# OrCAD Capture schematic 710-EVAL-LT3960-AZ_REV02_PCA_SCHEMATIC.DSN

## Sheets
1 PAGE1: size Custom; title: 2; company: ANALOG DEVICES; note: DEMO BOARD BILL OF MATERIALS; note: I  C TO CAN-PHYSICAL TRANSCEIVER
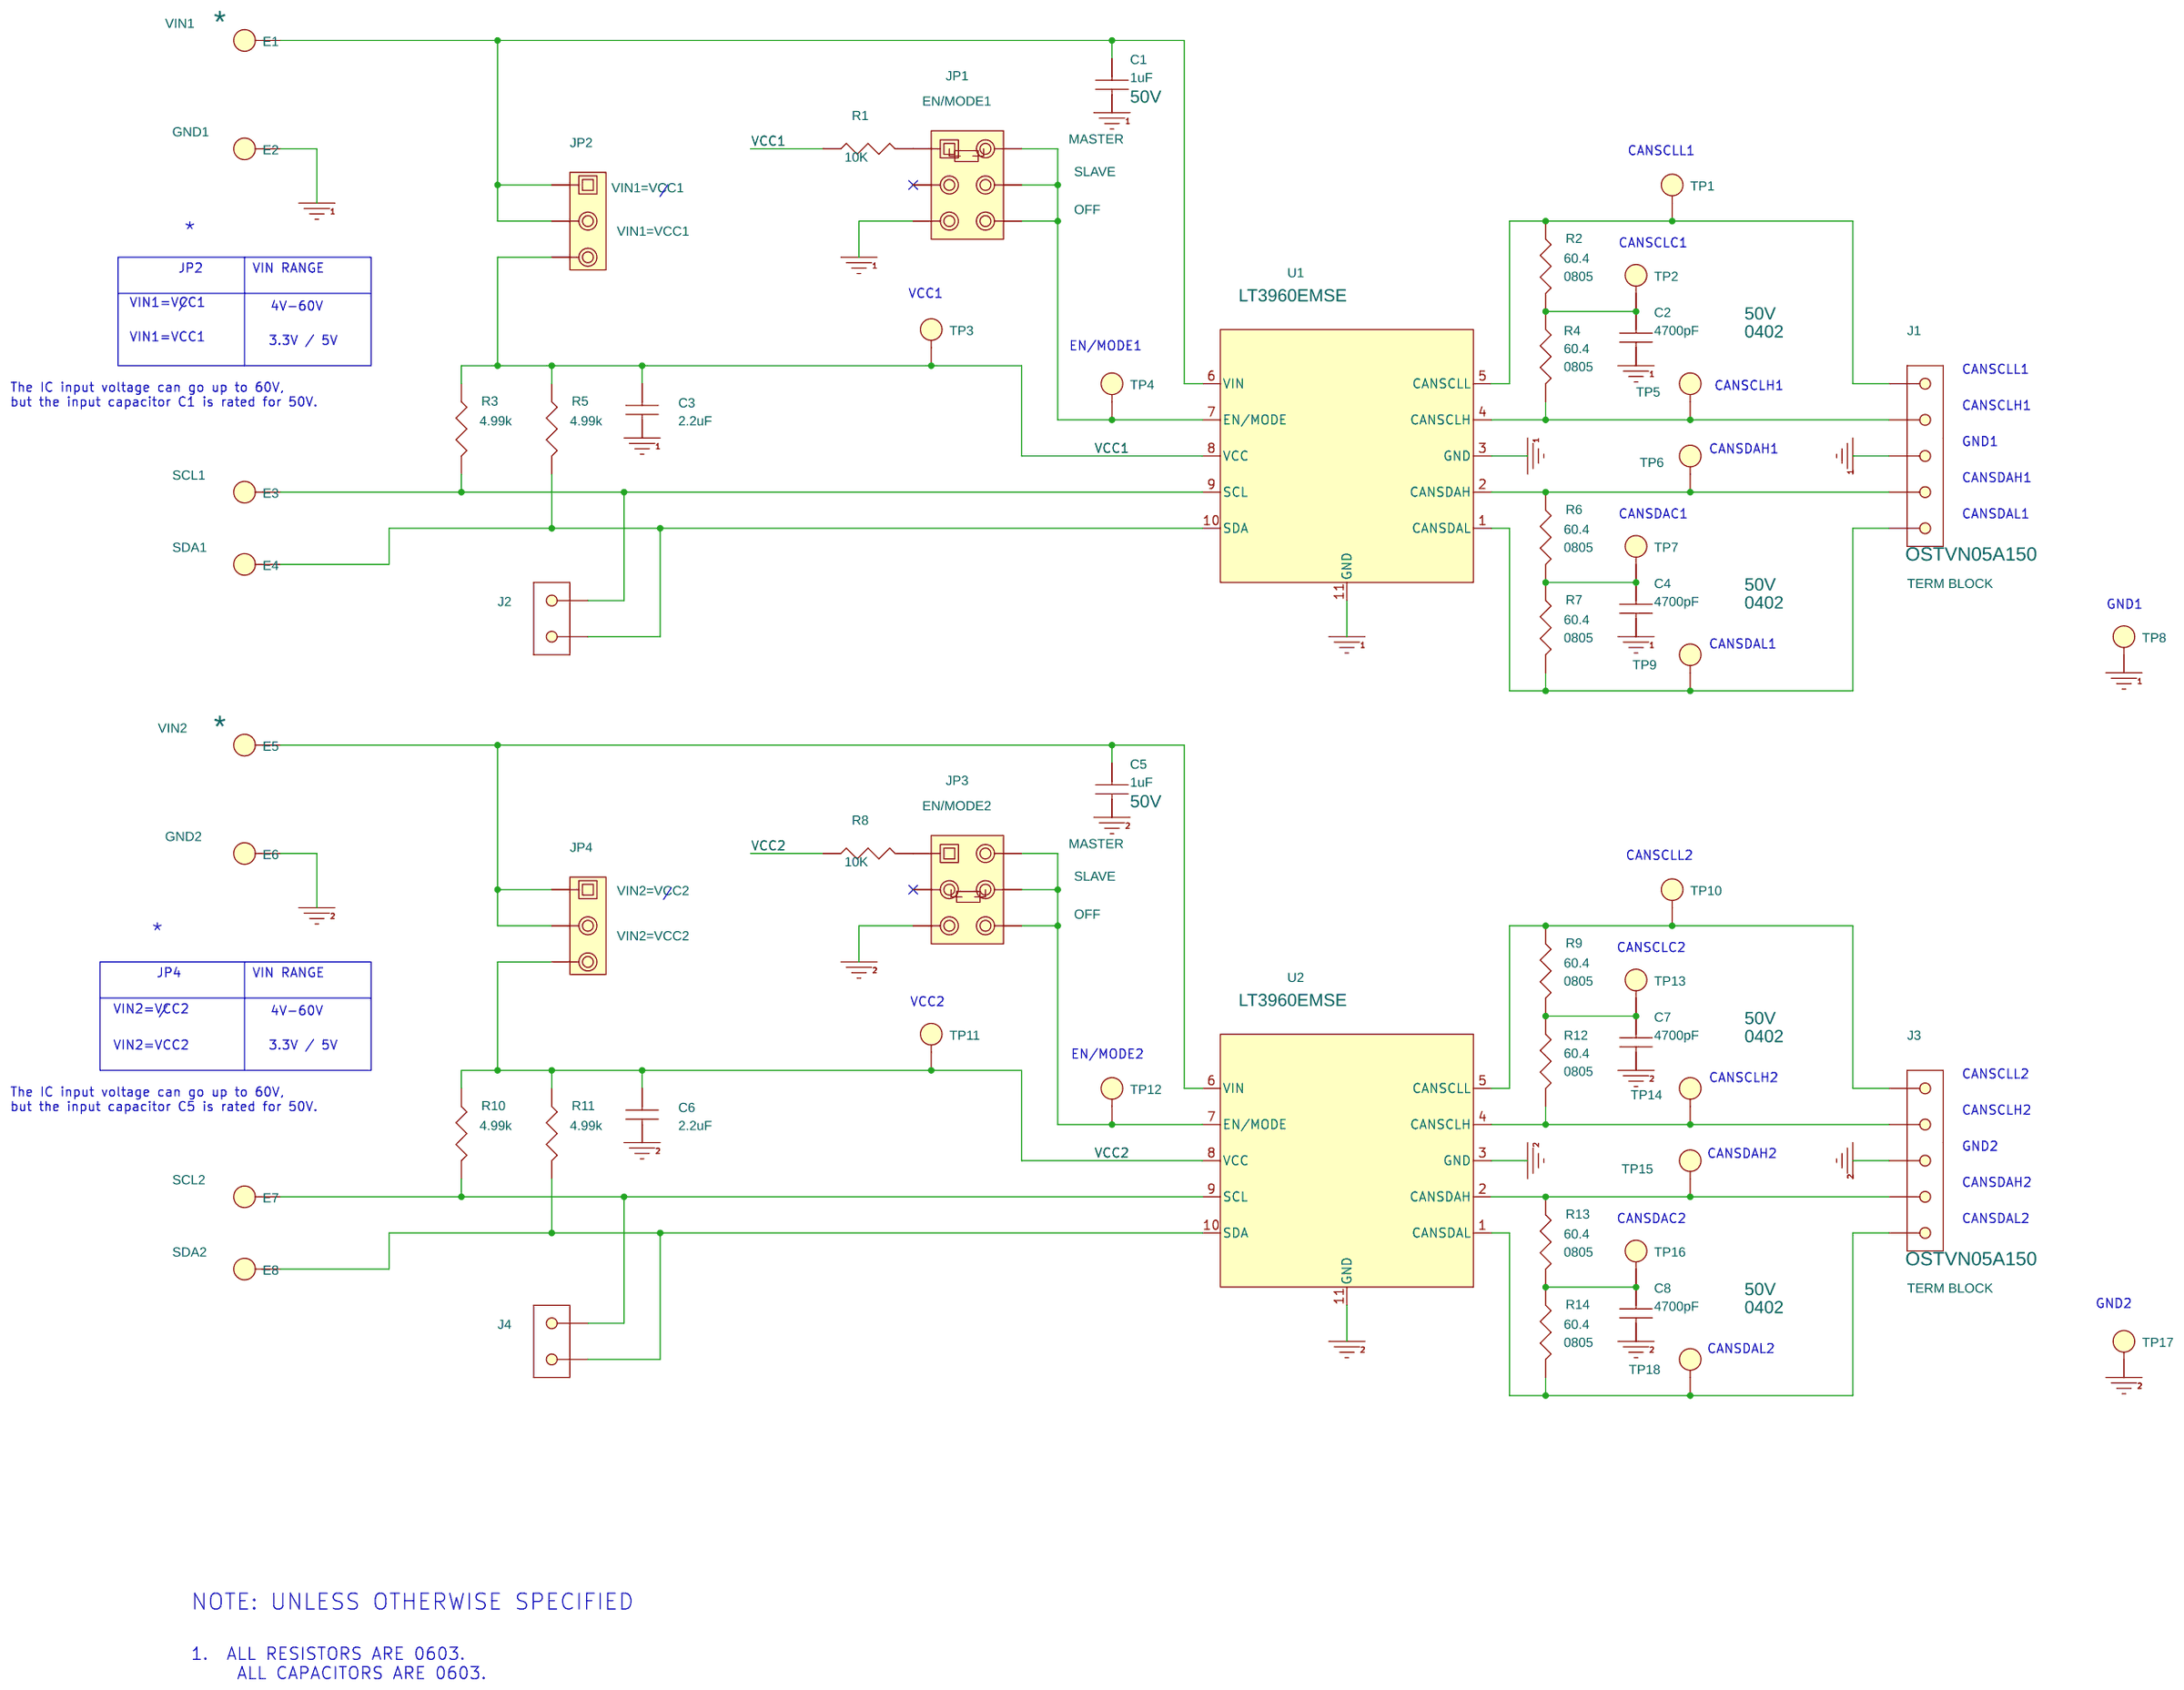
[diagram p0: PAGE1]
2 PAGE2 - HARDWARE
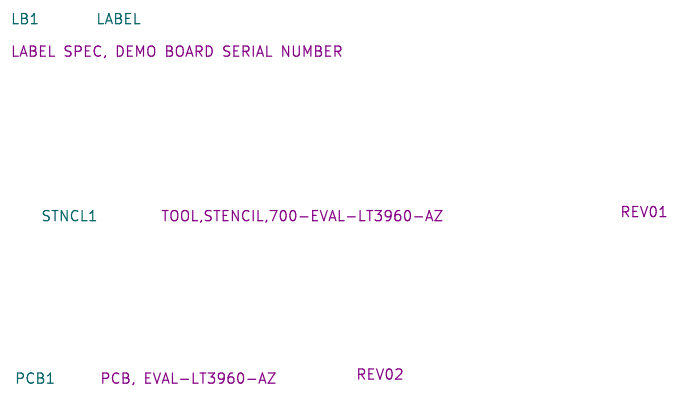
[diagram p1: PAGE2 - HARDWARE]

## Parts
sheet PAGE1
C1  1uF  [CC0603N]
C2  4700pF  [CC0402N]
C3  2.2uF  [CC0603N]
C4  4700pF  [CC0402N]
C5  1uF  [CC0603N]
C6  2.2uF  [CC0603N]
C7  4700pF  [CC0402N]
C8  4700pF  [CC0402N]
E1  TEST POINT  [MILLMAX2308]
E2  TEST POINT  [MILLMAX2308]
E3  TEST POINT  [MILLMAX2308]
E4  TEST POINT  [MILLMAX2308]
E5  TEST POINT  [MILLMAX2308]
E6  TEST POINT  [MILLMAX2308]
E7  TEST POINT  [MILLMAX2308]
E8  TEST POINT  [MILLMAX2308]
J1  TERM BLOCK  [OST-OSTVN05A150]
J2  HDR  [HD1X2-100]
J3  TERM BLOCK  [OST-OSTVN05A150]
J4  HDR  [HD1X2-100]
JP1  HDR  [HD2X3-079]
JP2  HDR  [HD1X3-079]
JP3  HDR  [HD2X3-079]
JP4  HDR  [HD1X3-079]
R1  10K  [CR0603N]
R2  60.4  [CR0805N]
R3  4.99k  [CR0603N]
R4  60.4  [CR0805N]
R5  4.99k  [CR0603N]
R6  60.4  [CR0805N]
R7  60.4  [CR0805N]
R8  10K  [CR0603N]
R9  60.4  [CR0805N]
R10  4.99k  [CR0603N]
R11  4.99k  [CR0603N]
R12  60.4  [CR0805N]
R13  60.4  [CR0805N]
R14  60.4  [CR0805N]
TP1  TEST POINT,1POS  [KEYSTONE-5000-5004]
TP2  TEST POINT,1POS  [KEYSTONE-5000-5004]
TP3  TEST POINT,1POS  [KEYSTONE-5000-5004]
TP4  TEST POINT,1POS  [KEYSTONE-5000-5004]
TP5  TEST POINT,1POS  [KEYSTONE-5000-5004]
TP6  TEST POINT,1POS  [KEYSTONE-5000-5004]
TP7  TEST POINT,1POS  [KEYSTONE-5000-5004]
TP8  TEST POINT,1POS  [KEYSTONE-5000-5004]
TP9  TEST POINT,1POS  [KEYSTONE-5000-5004]
TP10  TEST POINT,1POS  [KEYSTONE-5000-5004]
TP11  TEST POINT,1POS  [KEYSTONE-5000-5004]
TP12  TEST POINT,1POS  [KEYSTONE-5000-5004]
TP13  TEST POINT,1POS  [KEYSTONE-5000-5004]
TP14  TEST POINT,1POS  [KEYSTONE-5000-5004]
TP15  TEST POINT,1POS  [KEYSTONE-5000-5004]
TP16  TEST POINT,1POS  [KEYSTONE-5000-5004]
TP17  TEST POINT,1POS  [KEYSTONE-5000-5004]
TP18  TEST POINT,1POS  [KEYSTONE-5000-5004]
U1  LT3960-EMSE  [LTC-MSE-10-1664]
U2  LT3960-EMSE  [LTC-MSE-10-1664]
XJP1  SHUNT
XJP2  SHUNT
XJP3  SHUNT
XJP4  SHUNT
sheet PAGE2 - HARDWARE
LB1  LABEL  [895-0154_REV01]
PCB1  PCB, EVAL-LT3960-AZ
STNCL1  TOOL,STENCIL

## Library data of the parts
C1 C5 = CAP: CAP.,1uF,X7R,50V,10%,0603; CLASS: DISCRETE; Dielectric Type: X7R; FPLIST: CC0603N,CC0603L,CC0603M; Inventory Qty: 15823; Manufacturer: AVX; Manufacturer PN: 06035C105KAT2A; PART_NUMBER: 150-2333; Package Size: 0603; Rated Voltage: 50V; Tolerance: 10%
C2 C4 C7 C8 = CAP: CAP.,4700pF,X7R,50V,10%,0402; CLASS: DISCRETE; Dielectric Type: X7R; FPLIST: CC0402N,CC0402L,CC0402M; Inventory Qty: 13640; Manufacturer: AVX; Manufacturer PN: 04025C472KAT2A; PART_NUMBER: 150-0108; Package Size: 0402; Rated Voltage: 50V; Tolerance: 10%
C3 C6 = CAP: CAP.,2.2uF,X7S,10V,10%,0603,AEC-Q200; CLASS: DISCRETE; Dielectric Type: X7S; Inventory Qty: 3800; Manufacturer: TDK; Manufacturer PN: CGA3E3X7S1A225K080AB; PART_NUMBER: 150-1791; Package Size: 0603; Rated Voltage: 10V; Tolerance: 10%
E1 = TEST_POINT_.156_MILL-MAX_2308: TEST POINT,TURRET,0.064" MTG. HOLE,PCB 0.062" THK; 5TH PART FIELD: *; CLASS: IO; Inventory Qty: 1142083; Manufacturer: MILL-MAX; Manufacturer PN: 2308-2-00-80-00-00-07-0; PART_FIELD_1: VIN1; PART_NUMBER: 260-0004
E2 = TEST_POINT_.156_MILL-MAX_2308: TEST POINT,TURRET,0.064" MTG. HOLE,PCB 0.062" THK; CLASS: IO; Inventory Qty: 1142083; Manufacturer: MILL-MAX; Manufacturer PN: 2308-2-00-80-00-00-07-0; PART_FIELD_1: GND1; PART_NUMBER: 260-0004
E3 = TEST_POINT_.156_MILL-MAX_2308: TEST POINT,TURRET,0.064" MTG. HOLE,PCB 0.062" THK; CLASS: IO; Inventory Qty: 1142083; Manufacturer: MILL-MAX; Manufacturer PN: 2308-2-00-80-00-00-07-0; PART_FIELD_1: SCL1; PART_NUMBER: 260-0004
E4 = TEST_POINT_.156_MILL-MAX_2308: TEST POINT,TURRET,0.064" MTG. HOLE,PCB 0.062" THK; CLASS: IO; Inventory Qty: 1142083; Manufacturer: MILL-MAX; Manufacturer PN: 2308-2-00-80-00-00-07-0; PART_FIELD_1: SDA1; PART_NUMBER: 260-0004
E5 = TEST_POINT_.156_MILL-MAX_2308: TEST POINT,TURRET,0.064" MTG. HOLE,PCB 0.062" THK; 5TH PART FIELD: *; CLASS: IO; Inventory Qty: 1142083; Manufacturer: MILL-MAX; Manufacturer PN: 2308-2-00-80-00-00-07-0; PART_FIELD_1: VIN2; PART_NUMBER: 260-0004
E6 = TEST_POINT_.156_MILL-MAX_2308: TEST POINT,TURRET,0.064" MTG. HOLE,PCB 0.062" THK; CLASS: IO; Inventory Qty: 1142083; Manufacturer: MILL-MAX; Manufacturer PN: 2308-2-00-80-00-00-07-0; PART_FIELD_1: GND2; PART_NUMBER: 260-0004
E7 = TEST_POINT_.156_MILL-MAX_2308: TEST POINT,TURRET,0.064" MTG. HOLE,PCB 0.062" THK; CLASS: IO; Inventory Qty: 1142083; Manufacturer: MILL-MAX; Manufacturer PN: 2308-2-00-80-00-00-07-0; PART_FIELD_1: SCL2; PART_NUMBER: 260-0004
E8 = TEST_POINT_.156_MILL-MAX_2308: TEST POINT,TURRET,0.064" MTG. HOLE,PCB 0.062" THK; CLASS: IO; Inventory Qty: 1142083; Manufacturer: MILL-MAX; Manufacturer PN: 2308-2-00-80-00-00-07-0; PART_FIELD_1: SDA2; PART_NUMBER: 260-0004
J1 J3 = 1X5: CONN.,TERM BLOCK,5 POS,2.54mm,ST,THT,SIDE ENTRY,GREEN; CLASS: IO; Inventory Qty: 800; Manufacturer: ON-SHORE TECHNOLOGY; Manufacturer PN: OSTVN05A150; PART_NUMBER: 250-0956
J2 J4 = HDR1X2: CONN.,HDR,MALE,1x2,2.54mm,VERT,ST,THT; CLASS: IO; Inventory Qty: 990; Manufacturer: WURTH ELEKTRONIK; Manufacturer PN: 61300211121; PART_NUMBER: 250-0766
JP1 = HDR2X3_ALT1: CONN.,HDR,MALE,2x3,2mm,VERT,ST,THT; 10th Part Field: MASTER; 11th Part Field: SLAVE; 12th Part Field: OFF; 9th Part Field: EN/MODE1; CLASS: IO; Inventory Qty: 17651; Manufacturer: WURTH ELEKTRONIK; Manufacturer PN: 62000621121; PART_NUMBER: 250-0483
JP2 = 1X3_A: CONN.,HDR,MALE,1x3,2mm,VERT,ST,THT,NO SUBS. ALLOWED; 10th Part Field: VIN1=VCC1; 9th Part Field: VIN1=VCC1; CLASS: IO; Inventory Qty: 28997; Manufacturer: Wurth Elektronik; Manufacturer PN: 62000311121; PART_NUMBER: 250-0639
JP3 = HDR2X3_ALT1: CONN.,HDR,MALE,2x3,2mm,VERT,ST,THT; 10th Part Field: MASTER; 11th Part Field: SLAVE; 12th Part Field: OFF; 9th Part Field: EN/MODE2; CLASS: IO; Inventory Qty: 17651; Manufacturer: WURTH ELEKTRONIK; Manufacturer PN: 62000621121; PART_NUMBER: 250-0483
JP4 = 1X3_A: CONN.,HDR,MALE,1x3,2mm,VERT,ST,THT,NO SUBS. ALLOWED; 10th Part Field: VIN2=VCC2; 9th Part Field: VIN2=VCC2; CLASS: IO; Inventory Qty: 28997; Manufacturer: Wurth Elektronik; Manufacturer PN: 62000311121; PART_NUMBER: 250-0639
R1 R8 = RES: RES.,10K OHMS,1%,1/10W,0603,AEC-Q200; CLASS: DISCRETE; FPLIST: CR0603N,CR0603L,CR0603M; Inventory Qty: 41873; Manufacturer: PANASONIC; Manufacturer PN: ERJ3EKF1002V; PART_NUMBER: 100-0602; Package Size: 0603; Rated Power: 1/10W; Temperature Coefficient: 100PPM; Tolerance: 1%
R2 R4 R6 R7 R9 R12-R14 = RES: RES.,60.4 OHMS,1%,1/8W,0805,AEC-Q200; CLASS: DISCRETE; FPLIST: CR0805N,CR0805L,CR0805M; Inventory Qty: 18592; Manufacturer: PANASONIC; Manufacturer PN: ERJ6ENF60R4V; PART_NUMBER: 100-1558; Package Size: 0805; Rated Power: 1/8W; Temperature Coefficient: +/-100ppm; Tolerance: 1%
R3 R5 R10 R11 = RES: RES.,4.99k OHMS,1%,1/10W,0603,AEC-Q200; CLASS: DISCRETE; FPLIST: CR0603N,CR0603L,CR0603M; Inventory Qty: 89391; Manufacturer: PANASONIC; Manufacturer PN: ERJ3EKF4991V; PART_NUMBER: 100-2510; Package Size: 0603; Rated Power: 1/10W; Temperature Coefficient: 100ppm; Tolerance: 1%
TP1-TP18 = TEST_POINT_.156_MILL-MAX_2308: TEST POINT,1POS,0.040" MTG. HOLE,2.54mm DIA x 4.57mm L,THT,BLACK; CLASS: DISCRETE; Inventory Qty: 0; Manufacturer: KEYSTONE; Manufacturer PN: 5001; PART_NUMBER: 260-2659
U1 U2 = LT3960-MSE: IC,12C TO DUAL CAN TRANSCEIVER,MSOP-10; 5TH PART FIELD: LT3960EMSE; CLASS: IC; Inventory Qty: 200; Manufacturer: ANALOG DEVICES; Manufacturer PN: LT3960EMSE#PBF; PART_NUMBER: LT3960EMSE#PBF; Package Size: MSOP-10; Package Type: MSOP-10
XJP1-XJP4 = SHUNT_2MM_C: CONN.,SHUNT,FEMALE,2 POS,2mm; CLASS: IO; Inventory Qty: 64675; Manufacturer: Wurth Elektronik; Manufacturer PN: 60800213421; PART_NUMBER: 250-0485
LB1 = BLANK_LABEL: LABEL SPEC, DEMO BOARD SERIAL NUMBER; Inventory Qty: 0; Manufacturer: BRADY; Manufacturer PN: THT-96-717-10; PART_NUMBER: 895-0154
PCB1 = BLANK_PCB_PART: BOM Notes: REV02; CLASS: DISCRETE; Inventory Qty: 0; Manufacturer: ADI APPROVED SUPPLIER; Manufacturer PN: 600-EVAL-LT3960-AZ; PART_NUMBER: 600-EVAL-LT3960-AZ
STNCL1 = BLANK_STENCIL_PART: TOOL,STENCIL,700-EVAL-LT3960-AZ; BOM Notes: REV01; CLASS: DISCRETE; Inventory Qty: 0; Manufacturer: ADI APPROVED SUPPLIER; Manufacturer PN: 830-EVAL-LT3960-AZ; PART_NUMBER: 830-EVAL-LT3960-AZ

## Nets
GNDA: C1.2 C2.2 C3.2 C4.2 E2.1(A) J1.3 JP1.5 TP8.1(A) U1.3(GND) U1.11(GND)
GNDB: C5.2 C6.2 C7.2 C8.2 E6.1(A) J3.3 JP3.5 TP17.1(A) U2.3(GND) U2.11(GND)
VCC1: C3.1 JP2.3 R1.1 R3.1 R5.1 TP3.1(A) U1.8(VCC)
VCC2: C6.1 JP4.3 R8.1 R10.1 R11.1 TP11.1(A) U2.8(VCC)
N1424249: J1.2 R6.1 TP6.1(A) U1.2(CANSDAH)
N1424253: J1.1 R7.2 TP9.1(A) U1.1(CANSDAL)
N1424270: J1.4 R4.2 TP5.1(A) U1.4(CANSCLH)
N1424274: J1.5 R2.1 TP1.1(A) U1.5(CANSCLL)
N1424387: C4.1 R6.2 R7.1 TP7.1(A)
N1424519: C2.1 R2.2 R4.1 TP2.1(A)
N1428206: C1.1 E1.1(A) JP2.1 JP2.2 U1.6(VIN)
N1429185: E3.1(A) J2.1 R3.2 U1.9(SCL)
N1429282: E4.1(A) J2.2 R5.2 U1.10(SDA)
N1505852: JP1.2 JP1.4 JP1.6 TP4.1(A) U1.7(EN/MODE)
N1514724: C5.1 E5.1(A) JP4.1 JP4.2 U2.6(VIN)
N1514850: JP3.2 JP3.4 JP3.6 TP12.1(A) U2.7(EN/MODE)
N1514950: J3.5 R9.1 TP10.1(A) U2.5(CANSCLL)
N1515036: C7.1 R9.2 R12.1 TP13.1(A)
N1515294: J3.4 R12.2 TP14.1(A) U2.4(CANSCLH)
N1515378: E7.1(A) J4.1 R10.2 U2.9(SCL)
N1515382: E8.1(A) J4.2 R11.2 U2.10(SDA)
N1515398: J3.2 R13.1 TP15.1(A) U2.2(CANSDAH)
N1515444: J3.1 R14.2 TP18.1(A) U2.1(CANSDAL)
N1515502: C8.1 R13.2 R14.1 TP16.1(A)
N1528023: JP1.1 R1.2
N1528087: JP3.1 R8.2

Not connected (* = marked no-connect by the designer): JP1 3*; JP3 3*

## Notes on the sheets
sheet 1
- CANSCLL1
- /
- *
- CANSCLC1
- JP2
- VIN RANGE
- VCC1
- VIN1=VCC1
- /
- 4V-60V
- VIN1=VCC1
- 3.3V / 5V
- EN/MODE1
- CANSCLL1
- The IC input voltage can go up to 60V,
  but the input capacitor C1 is rated for 50V.
- CANSCLH1
- CANSCLH1
- GND1
- CANSDAH1
- CANSDAH1
- CANSDAC1
- CANSDAL1
- GND1
- CANSDAL1
- CANSCLL2
- /
- *
- CANSCLC2
- JP4
- VIN RANGE
- VIN2=VCC2
- /
- 4V-60V
- VCC2
- VIN2=VCC2
- 3.3V / 5V
- EN/MODE2
- CANSCLH2
- CANSCLL2
- The IC input voltage can go up to 60V,
  but the input capacitor C5 is rated for 50V.
- CANSCLH2
- GND2
- CANSDAH2
- CANSDAH2
- CANSDAC2
- CANSDAL2
- GND2
- CANSDAL2
- NOTE: UNLESS OTHERWISE SPECIFIED
- 1.  ALL RESISTORS ARE 0603.
       ALL CAPACITORS ARE 0603.
